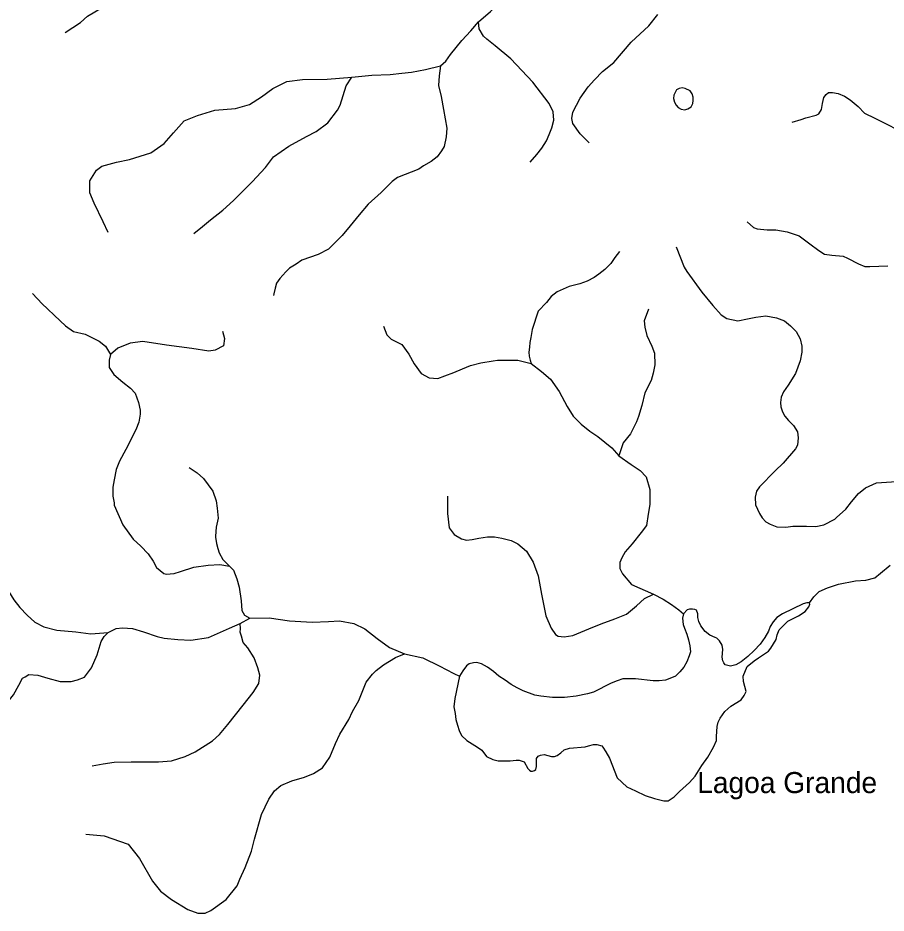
# Model space of a CAD drawing. Extents: x 436.3 to 500.4, y 8231 to 8286.4.
# Drawn here: x 471.41 to 478.01, y 8231.45 to 8238.26 of the extents above; entities that cross this region are included whole.
import ezdxf

# ---------------------------------------------------------------- set-up
doc = ezdxf.new("R2010")
doc.units = 0
doc.header["$LTSCALE"] = 0.08
doc.linetypes.add('LONG_DASHED', pattern=[7.5, 6, -1.5])
doc.layers.add('2', color=7, linetype='Continuous', lineweight=25)
doc.layers.add('9', color=7, linetype='LONG_DASHED', lineweight=25)
doc.layers.add('61', color=7, linetype='Continuous')

msp = doc.modelspace()

# ---------------------------------------------------------------- linework, layer by layer
at = {"layer": '2'}
msp.add_lwpolyline([(476.3944, 8237.6712), (476.3921, 8237.646), (476.3987, 8237.6164), (476.4119, 8237.5945), (476.4273, 8237.5759), (476.4492, 8237.5638), (476.4778, 8237.5594), (476.5021, 8237.566), (476.5252, 8237.5824), (476.5396, 8237.6074), (476.5407, 8237.6305), (476.5407, 8237.6546), (476.5331, 8237.6809), (476.5177, 8237.7038), (476.4803, 8237.7225), (476.4583, 8237.7258), (476.4352, 8237.7225), (476.4154, 8237.7105), (476.4076, 8237.6963)], close=True, dxfattribs=at)
for points in [[(474.7642, 8233.2534), (474.7299, 8233.0835), (474.7214, 8233.0201), (474.7308, 8232.9687), (474.7353, 8232.9237), (474.7489, 8232.8787), (474.7624, 8232.8382), (474.7805, 8232.8022), (474.821, 8232.7618), (474.902, 8232.7124), (474.9335, 8232.6899), (474.9696, 8232.6404), (475.0191, 8232.618), (475.0595, 8232.609), (475.1495, 8232.6091), (475.1944, 8232.6136), (475.2169, 8232.6137), (475.2574, 8232.6002), (475.2845, 8232.5507), (475.2962, 8232.5368), (475.3077, 8232.5311), (475.3192, 8232.5311), (475.3336, 8232.5339), (475.3452, 8232.5427), (475.3508, 8232.5657), (475.3507, 8232.6262), (475.3622, 8232.6434), (475.3794, 8232.6521), (475.4082, 8232.6578), (475.463, 8232.6406), (475.486, 8232.6406), (475.5062, 8232.6493), (475.5349, 8232.6694), (475.5609, 8232.6926), (475.6011, 8232.7041), (475.7192, 8232.7156), (475.7451, 8232.7214), (475.7825, 8232.7329), (475.8085, 8232.7329), (475.8459, 8232.7214), (475.8546, 8232.7128), (475.878, 8232.6771), (475.905, 8232.6276), (475.9638, 8232.479), (476.0359, 8232.4115), (476.1035, 8232.38), (476.1755, 8232.344), (476.2476, 8232.3215), (476.3196, 8232.3035), (476.3511, 8232.3035), (476.396, 8232.335), (476.4365, 8232.3755), (476.5128, 8232.443), (476.5577, 8232.4925), (476.6071, 8232.5735), (476.6519, 8232.6365), (476.6968, 8232.713), (476.7192, 8232.7625), (476.7191, 8232.794), (476.7235, 8232.8705), (476.7324, 8232.902), (476.7459, 8232.9335), (476.7818, 8232.983), (476.8267, 8233.0235), (476.9076, 8233.0729), (476.9301, 8233.1044), (476.9435, 8233.1359), (476.9254, 8233.2124), (476.9208, 8233.2529), (476.9522, 8233.3249), (477.0061, 8233.3699), (477.0376, 8233.3923), (477.114, 8233.4418), (477.132, 8233.4642), (477.1724, 8233.5317), (477.1813, 8233.5677), (477.1948, 8233.6037), (477.2622, 8233.6711), (477.3431, 8233.7114), (477.3926, 8233.7429), (477.4224, 8233.779), (477.428, 8233.7992), (477.4252, 8233.8107)], [(477.4252, 8233.8107), (477.405, 8233.8107), (477.3791, 8233.8022), (477.2216, 8233.7251), (477.1766, 8233.6982), (477.1497, 8233.6667), (477.1272, 8233.6307), (477.1138, 8233.5948), (477.0868, 8233.5453), (477.0509, 8233.4958), (477.006, 8233.4464), (476.9566, 8233.4014), (476.9071, 8233.361)], [(476.4668, 8233.7269), (476.461, 8233.6944), (476.4656, 8233.6448), (476.4747, 8233.6178), (476.4927, 8233.5728), (476.5063, 8233.5278), (476.5154, 8233.4828), (476.52, 8233.4378), (476.511, 8233.4063), (476.4931, 8233.3613), (476.4707, 8233.3208), (476.4392, 8233.2848), (476.4078, 8233.2533), (476.3763, 8233.2398), (476.3314, 8233.2218), (476.2819, 8233.2173), (476.2369, 8233.2173), (476.1019, 8233.2308), (476.0074, 8233.2308), (475.9625, 8233.2173), (475.9175, 8233.1993), (475.7827, 8233.1317), (475.7377, 8233.1182), (475.6523, 8233.1001), (475.5624, 8233.0911), (475.4724, 8233.091), (475.3825, 8233.1), (475.3375, 8233.1089), (475.2475, 8233.1404), (475.2025, 8233.1628), (475.1575, 8233.1898), (475.1125, 8233.2212), (475.063, 8233.2527), (475.0225, 8233.2887), (474.9775, 8233.3201), (474.9325, 8233.3471), (474.8965, 8233.356), (474.8705, 8233.3543), (474.8389, 8233.3456), (474.8187, 8233.3312), (474.79, 8233.2938), (474.7642, 8233.2534)], [(476.763, 8233.397), (476.7674, 8233.4556), (476.7629, 8233.4871), (476.7423, 8233.5198), (476.7221, 8233.5401), (476.7077, 8233.5458), (476.6674, 8233.5631), (476.6327, 8233.5919), (476.6009, 8233.6351), (476.5836, 8233.6668), (476.5777, 8233.6985), (476.5777, 8233.7272), (476.5661, 8233.7531), (476.5546, 8233.7589), (476.5373, 8233.7618), (476.5142, 8233.7618), (476.497, 8233.756), (476.4668, 8233.7269)], [(476.9071, 8233.361), (476.8667, 8233.3385), (476.8262, 8233.3295), (476.7856, 8233.3386), (476.7746, 8233.3539), (476.7659, 8233.3683), (476.763, 8233.397)]]:
    msp.add_lwpolyline(points, dxfattribs=at)
at = {"layer": '9'}
for points in [[(471.7648, 8238.1469), (471.8807, 8238.2242), (471.9347, 8238.2705), (472.0467, 8238.3362), (472.1355, 8238.3942), (472.2242, 8238.4559), (472.3593, 8238.5178), (472.4674, 8238.599), (472.5485, 8238.6647), (472.6064, 8238.7458), (472.6837, 8238.8192), (472.7184, 8238.8848), (472.7571, 8238.9582), (472.7879, 8238.9929), (472.8381, 8239.0278), (472.8998, 8239.0588), (472.9809, 8239.086), (473.0233, 8239.0938), (473.0773, 8239.094), (473.1892, 8239.0827), (473.2935, 8239.0521), (473.4092, 8239.0254), (473.5057, 8238.9794), (473.5641, 8238.9133)], [(474.9097, 8238.2279), (475.0005, 8238.3068), (475.0677, 8238.3738), (475.1546, 8238.4486), (475.2072, 8238.5008), (475.2534, 8238.6023), (475.2733, 8238.6848), (475.3072, 8238.7873)], [(475.7508, 8237.3081), (475.6809, 8237.3777), (475.6266, 8237.4551), (475.6189, 8237.4938), (475.6267, 8237.5403), (475.6813, 8237.6487), (475.7437, 8237.7339), (475.7904, 8237.7881), (475.8527, 8237.8501), (475.9385, 8237.9198), (476.071, 8238.0747), (476.2034, 8238.1985), (476.2737, 8238.2838)], [(474.6195, 8237.8928), (474.6608, 8237.9286), (474.6964, 8237.9798), (474.7833, 8238.0862), (474.8505, 8238.1609), (474.9097, 8238.2279)], [(475.3022, 8237.1599), (475.3517, 8237.2191), (475.3913, 8237.2684), (475.4261, 8237.3226), (475.4459, 8237.3719), (475.4658, 8237.4211), (475.4806, 8237.4802), (475.4758, 8237.5443), (475.4462, 8237.6083), (475.3227, 8237.7707), (475.2388, 8237.8593), (475.1548, 8237.9479), (475.0363, 8238.0463), (474.9721, 8238.0956), (474.9474, 8238.1201), (474.9128, 8238.1743), (474.9097, 8238.2279)], [(474.6195, 8237.8928), (474.6096, 8237.8188), (474.6046, 8237.745), (474.6241, 8237.66), (474.6437, 8237.5615), (474.6683, 8237.4186), (474.6633, 8237.3546), (474.6484, 8237.2806), (474.6286, 8237.2461), (474.5939, 8237.2017), (474.5495, 8237.1671), (474.4902, 8237.1325), (474.4555, 8237.1078), (474.2924, 8237.0433), (474.2529, 8237.0136), (474.1689, 8236.9296), (474.07, 8236.8406), (474.0008, 8236.7616), (473.9316, 8236.6775), (473.8723, 8236.6035), (473.813, 8236.5441), (473.7686, 8236.4996), (473.6895, 8236.4599), (473.566, 8236.4152), (473.5216, 8236.3855), (473.4722, 8236.3558), (473.4425, 8236.3261), (473.398, 8236.2767), (473.3734, 8236.2421), (473.3635, 8236.2026)], [(473.9443, 8237.8068), (474.0969, 8237.8226), (474.2383, 8237.8284), (474.3255, 8237.8373), (474.4004, 8237.8454), (474.5069, 8237.8652), (474.6195, 8237.8928)], [(472.0936, 8236.6261), (472.0533, 8236.7069), (471.9846, 8236.8483), (471.9523, 8236.9288), (471.9523, 8237.0198), (472.003, 8237.1006), (472.0434, 8237.1309), (472.1546, 8237.1615), (472.2558, 8237.1819), (472.4176, 8237.2328), (472.5188, 8237.3037), (472.5896, 8237.3846), (472.6706, 8237.4756), (472.7717, 8237.5163), (472.8366, 8237.536), (472.9032, 8237.557), (473.0613, 8237.5681), (473.1677, 8237.5997), (473.2573, 8237.6589), (473.3456, 8237.7225), (473.4521, 8237.774), (473.5709, 8237.7909), (473.7582, 8237.7927), (473.9443, 8237.8068)], [(472.7441, 8236.6193), (472.8105, 8236.6711), (472.8695, 8236.7227), (472.9654, 8236.7965), (473.0466, 8236.8704), (473.1866, 8237.0106), (473.2899, 8237.1213), (473.349, 8237.2024), (473.467, 8237.2836), (473.5997, 8237.3575), (473.6734, 8237.3945), (473.7619, 8237.461), (473.8358, 8237.5568), (473.8579, 8237.5936), (473.9023, 8237.7409), (473.9443, 8237.8068)], [(477.2946, 8237.4658), (477.3621, 8237.4868), (477.3975, 8237.4973), (477.4758, 8237.5183), (477.4971, 8237.5288), (477.5184, 8237.5605), (477.5256, 8237.6063), (477.5364, 8237.6522), (477.5542, 8237.6769), (477.5719, 8237.691), (477.6003, 8237.6909), (477.643, 8237.6837), (477.6926, 8237.6623), (477.7352, 8237.634), (477.7955, 8237.5844), (477.8451, 8237.5349), (477.9232, 8237.4958), (478.0154, 8237.4497), (478.0934, 8237.4106), (478.1608, 8237.3539), (478.2069, 8237.3184), (478.2637, 8237.2936), (478.3133, 8237.2934)], [(476.9524, 8236.7068), (476.9991, 8236.6644), (477.029, 8236.6532), (477.1037, 8236.6456), (477.171, 8236.6454), (477.257, 8236.6303), (477.3466, 8236.6003), (477.4288, 8236.5406), (477.496, 8236.4883), (477.5408, 8236.4622), (477.5969, 8236.4546), (477.6828, 8236.4469), (477.7164, 8236.4319), (477.7987, 8236.387), (477.8472, 8236.3683), (477.8845, 8236.3682), (478.0229, 8236.3715)], [(476.4122, 8236.5179), (476.473, 8236.3625), (476.4934, 8236.3287), (476.6086, 8236.1731), (476.6899, 8236.0717), (476.7553, 8236.0005), (476.7984, 8235.9729), (476.8815, 8235.9542), (476.9554, 8235.9694), (477.017, 8235.9815), (477.094, 8235.9936), (477.1741, 8235.9781), (477.2357, 8235.9534), (477.2819, 8235.9164), (477.325, 8235.8734), (477.3557, 8235.8182), (477.368, 8235.7628), (477.368, 8235.7168), (477.3556, 8235.6494), (477.3187, 8235.5544), (477.2633, 8235.4655), (477.2293, 8235.4134), (477.2109, 8235.3736), (477.2047, 8235.3336), (477.2078, 8235.2999), (477.2202, 8235.263), (477.2387, 8235.2292), (477.2664, 8235.1954), (477.3033, 8235.1584), (477.3347, 8235.1104), (477.3409, 8235.0644), (477.3347, 8235.0091), (477.3193, 8234.9815), (477.227, 8234.8711), (477.1656, 8234.8129), (477.0455, 8234.6933), (477.024, 8234.6595), (477.0118, 8234.6135), (477.0149, 8234.5551), (477.0457, 8234.4905), (477.0674, 8234.4567), (477.0951, 8234.4259), (477.1259, 8234.4074), (477.1783, 8234.3889), (477.246, 8234.3857), (477.2983, 8234.3918), (477.4039, 8234.3939), (477.4747, 8234.3908), (477.5362, 8234.4029), (477.6193, 8234.4457), (477.6316, 8234.458), (477.7024, 8234.5224), (477.7454, 8234.5775), (477.7977, 8234.642), (477.8531, 8234.6848), (477.9362, 8234.7214), (478.0871, 8234.7333)], [(475.9817, 8236.4812), (475.946, 8236.4355), (475.9152, 8236.3896), (475.8692, 8236.3439), (475.8233, 8236.3083), (475.7875, 8236.2828), (475.7364, 8236.2573), (475.6803, 8236.2369), (475.5985, 8236.2165), (475.5067, 8236.1757), (475.4608, 8236.14), (475.425, 8236.094), (475.3637, 8236.0278), (475.3175, 8235.8896), (475.3059, 8235.8267), (475.2988, 8235.7891), (475.2964, 8235.7538), (475.2917, 8235.7162), (475.2941, 8235.6857), (475.3011, 8235.655), (475.3082, 8235.6292)], [(471.5166, 8236.1629), (471.5906, 8236.084), (471.6302, 8236.0446), (471.6846, 8235.9953), (471.7685, 8235.9164), (471.8278, 8235.8722), (471.9167, 8235.8526), (472.0232, 8235.8007), (472.0729, 8235.7625), (472.1097, 8235.6992)], [(473.3635, 8236.2026), (473.3511, 8236.1589), (473.3503, 8236.1473)], [(476.2022, 8236.0435), (476.1699, 8235.955), (476.1739, 8235.9068), (476.19, 8235.8424), (476.2264, 8235.7619), (476.2465, 8235.7096), (476.2506, 8235.6211), (476.2385, 8235.5567), (476.2224, 8235.5004), (476.174, 8235.4078), (476.1499, 8235.3112), (476.1257, 8235.2266), (476.1097, 8235.1864), (476.0652, 8235.0963), (476.0088, 8235.0279), (475.9767, 8234.9272)], [(474.1857, 8235.9142), (474.2124, 8235.8476), (474.2458, 8235.8143), (474.3259, 8235.7745), (474.3794, 8235.7012), (474.4194, 8235.6279), (474.4729, 8235.5546), (474.533, 8235.5214), (474.5999, 8235.5149), (474.6533, 8235.5351), (474.7201, 8235.5619), (474.7869, 8235.5888), (474.847, 8235.6156), (474.9273, 8235.6359), (475.0208, 8235.6494), (475.0541, 8235.6561), (475.2079, 8235.6564), (475.3082, 8235.6292)], [(472.9621, 8235.8749), (472.976, 8235.8199), (472.969, 8235.7649), (472.907, 8235.7303), (472.8588, 8235.7232), (472.728, 8235.7435), (472.535, 8235.7706), (472.356, 8235.7976), (472.2595, 8235.7835), (472.1654, 8235.747), (472.1097, 8235.6992)], [(472.1097, 8235.6992), (472.0997, 8235.6547), (472.0997, 8235.6004), (472.1343, 8235.5461), (472.2035, 8235.487), (472.2627, 8235.4427), (472.2973, 8235.4033), (472.3221, 8235.3342), (472.3368, 8235.275), (472.3368, 8235.2454), (472.3266, 8235.1848), (472.302, 8235.1255), (472.2278, 8234.9771), (472.1784, 8234.888), (472.1537, 8234.8237), (472.1389, 8234.7446), (472.129, 8234.6903), (472.129, 8234.6211), (472.1389, 8234.5716), (472.1389, 8234.5519), (472.2031, 8234.4038), (472.2823, 8234.2952), (472.3416, 8234.241), (472.396, 8234.1818), (472.4355, 8234.1275), (472.4603, 8234.0781), (472.5147, 8234.0338), (472.5344, 8234.0289), (472.5938, 8234.034), (472.6432, 8234.0489), (472.7435, 8234.0819), (472.8523, 8234.097), (472.9412, 8234.1022), (473.0154, 8234.0876)], [(475.3082, 8235.6292), (475.3884, 8235.57), (475.4553, 8235.51), (475.5221, 8235.4165), (475.5824, 8235.303), (475.6292, 8235.2296), (475.6895, 8235.1695), (475.7564, 8235.1161), (475.8166, 8235.076), (475.9238, 8234.9892), (475.9767, 8234.9272)], [(475.9767, 8234.9272), (476.071, 8234.8621), (476.1381, 8234.8153), (476.1849, 8234.7685), (476.2118, 8234.6726), (476.2119, 8234.5589), (476.1986, 8234.4853), (476.1853, 8234.3985), (476.1453, 8234.345), (476.0784, 8234.2581), (476.025, 8234.1979), (475.9983, 8234.1511), (475.9849, 8234.1176), (475.985, 8234.0708), (476.0052, 8234.0306), (476.0721, 8233.9504), (476.2396, 8233.8769)], [(472.7082, 8234.8389), (472.7702, 8234.7977), (472.8185, 8234.7565), (472.8529, 8234.7083), (472.8873, 8234.6602), (472.9149, 8234.5845), (472.9218, 8234.5294), (472.9287, 8234.4536), (472.9149, 8234.3846), (472.9081, 8234.3157), (472.9081, 8234.3088), (472.915, 8234.2607), (472.9252, 8234.2234), (472.9353, 8234.1912), (472.9654, 8234.1389), (473.0154, 8234.0876)], [(474.6725, 8234.6203), (474.6726, 8234.4889), (474.6867, 8234.381), (474.7244, 8234.3294), (474.7808, 8234.2967), (474.8183, 8234.2873), (474.8606, 8234.2921), (474.9122, 8234.3016), (474.9779, 8234.3111), (475.0295, 8234.3112), (475.0859, 8234.3019), (475.1563, 8234.2832), (475.208, 8234.2597), (475.2738, 8234.2035), (475.3255, 8234.1191), (475.3632, 8234.0158), (475.3869, 8233.8749), (475.42, 8233.7105), (475.4625, 8233.6166), (475.4954, 8233.5697), (475.5143, 8233.5556), (475.5612, 8233.5509), (475.627, 8233.5604), (475.749, 8233.6121), (475.8429, 8233.6497), (475.9462, 8233.6873), (476.0354, 8233.7249), (476.1105, 8233.786), (476.1715, 8233.8423), (476.2396, 8233.8769)], [(471.1421, 8234.4058), (471.1582, 8234.3225), (471.2176, 8234.1347), (471.3016, 8233.952), (471.3758, 8233.8335), (471.4213, 8233.7756), (471.4757, 8233.7163), (471.535, 8233.6621), (471.6043, 8233.6275), (471.7031, 8233.603), (471.8465, 8233.5884), (471.9601, 8233.5739), (472.0936, 8233.584)], [(473.0154, 8234.0876), (473.0451, 8234.0579), (473.0698, 8233.9937), (473.0897, 8233.9294), (473.1045, 8233.8256), (473.1096, 8233.7515), (473.1294, 8233.7169), (473.1698, 8233.6928)], [(477.4252, 8233.8107), (477.4583, 8233.8553), (477.4995, 8233.8964), (477.5624, 8233.9238), (477.6468, 8233.9512), (477.7765, 8233.9764), (477.8552, 8233.9821), (477.9221, 8233.9997), (477.9653, 8234.0349), (478.0388, 8234.0962)], [(476.2396, 8233.8769), (476.3132, 8233.8366), (476.3775, 8233.7978), (476.4327, 8233.7558), (476.4668, 8233.7269)], [(471.9707, 8232.5714), (472.0538, 8232.5855), (472.1369, 8232.5994), (472.2685, 8232.5997), (472.4764, 8232.6001), (472.5733, 8232.6073), (472.6772, 8232.642), (472.7533, 8232.6769), (472.8849, 8232.7602), (472.9403, 8232.8089), (473.0025, 8232.8852), (473.1202, 8233.031), (473.1962, 8233.1282), (473.2378, 8233.1975), (473.2446, 8233.2599), (473.2307, 8233.3154), (473.203, 8233.3915), (473.1544, 8233.4676), (473.1197, 8233.509), (473.1058, 8233.5576), (473.0961, 8233.5881), (473.0977, 8233.6122), (473.0965, 8233.6522)], [(472.0936, 8233.584), (472.1529, 8233.6138), (472.2024, 8233.6188), (472.2765, 8233.6141), (472.3606, 8233.5895), (472.4644, 8233.5552), (472.5188, 8233.5405), (472.6226, 8233.5308), (472.7215, 8233.526), (472.855, 8233.5461), (472.9242, 8233.576), (473.0159, 8233.6161), (473.0965, 8233.6522), (473.1698, 8233.6928)], [(473.1698, 8233.6928), (473.3169, 8233.6964), (473.4711, 8233.6723), (473.644, 8233.6633), (473.7674, 8233.6672), (473.8515, 8233.6723), (473.9603, 8233.6528), (474.0444, 8233.6133), (474.1385, 8233.5393), (474.2325, 8233.4702), (474.3464, 8233.4209)], [(471.1532, 8232.8533), (471.2384, 8232.9334), (471.2863, 8232.992), (471.3236, 8233.0507), (471.3715, 8233.1095), (471.4141, 8233.1841), (471.4407, 8233.2375), (471.4621, 8233.2481), (471.4887, 8233.2641), (471.558, 8233.259), (471.6325, 8233.2378), (471.7285, 8233.2113), (471.8106, 8233.2129), (471.8586, 8233.2235), (471.9119, 8233.245), (471.9651, 8233.3144), (472.0077, 8233.4157), (472.0396, 8233.517), (472.0609, 8233.5544), (472.0936, 8233.584)], [(471.9226, 8232.0517), (472.0612, 8232.0382), (472.2441, 8231.9738), (472.3315, 8231.8654), (472.4287, 8231.6924), (472.4911, 8231.6164), (472.5744, 8231.5541), (472.6992, 8231.4781), (472.7754, 8231.4505), (472.831, 8231.4506), (472.8725, 8231.4715), (472.9901, 8231.5548), (473.0732, 8231.6588), (473.0939, 8231.7075), (473.1354, 8231.7976), (473.1837, 8231.9223), (473.2045, 8232.0125), (473.2597, 8232.1997), (473.3149, 8232.3176), (473.3564, 8232.3801), (473.4049, 8232.4217), (473.488, 8232.4566), (473.585, 8232.4845), (473.6542, 8232.5123), (473.7235, 8232.554), (473.7788, 8232.6373), (473.8202, 8232.7414), (473.8548, 8232.8107), (473.9239, 8232.9218), (473.9516, 8232.9842), (474, 8233.0674), (474.0553, 8233.2062), (474.1036, 8233.2686), (474.1314, 8233.2964), (474.1867, 8233.3382), (474.2767, 8233.3937), (474.3464, 8233.4209)], [(474.3464, 8233.4209), (474.485, 8233.3916), (474.6137, 8233.3274), (474.6632, 8233.3028), (474.7225, 8233.2732), (474.7642, 8233.2534)]]:
    msp.add_lwpolyline(points, dxfattribs=at)

# ---------------------------------------------------------------- texts
at = {"layer": '61'}
msp.add_text('Lagoa Grande     ', height=0.16, dxfattribs=at).set_placement((476.5724, 8232.3631))

doc.saveas('drawing.dxf')
